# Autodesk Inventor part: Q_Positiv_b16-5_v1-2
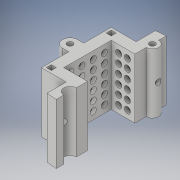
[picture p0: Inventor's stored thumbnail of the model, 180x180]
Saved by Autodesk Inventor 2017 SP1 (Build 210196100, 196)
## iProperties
Part Number: Q_Positiv_b16-5_v1-2
Material: Generisch
Document SubType Name: Modeling
Designer: haesner
Density: 1 g/cm^3
Appearance: Vorgabe
Part Number: Q_Positiv_b16-5_v1-2_3D-Druck
Author: haesner
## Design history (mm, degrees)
sketch "Skizze1"
  geometry: L1 (0, 9.5)-(-9.5, 9.5); L2 (-9.5, 9.5)-(-9.5, -9.5); L3 (-9.5, -9.5)-(0, -9.5); L4 (-26.9, 0)-(7.4, 0) reference; L5 (0, -9.5)-(0, -14); L6 (0, -22)-(0, -19); L7 (0, 22)-(0, 19); L8 (0, 14)-(0, 9.5); L9 (0, -30.8)-(0, 30.8) reference; C1 r 1.15 at (-16.5, 0); C2 r 1.15 at (0, 16.5); A1 r 22 centre (0, 0) between (0, 22) and (0, -22); A2 r 2.5 centre (0, -16.5) between (0, -14) and (0, -19); A3 r 2.5 centre (0, 16.5) between (0, 14) and (0, 19); 1 further point
  constraints: 14 end point, 6 point on circle, 5 centre point, 5 collinear, 3 point on line, 3 vertical, 2 coincident, 2 equal radius, 1 horizontal, 1 perpendicular, 1 other
  dimensions: "d1" = 22 radius of A1; "d5" = 2.3 diameter of C2; "d7" = 2.5 radius of A2; "d8" = 16.5 distance from line of L4 A3.centre (= d9); "d9" = 16.5 distance from line of L4 A2.centre; "d10" = 16.5 distance from line of C1.centre L9 (= d9); "d11" = 9.5 distance between parallel lines of L9 L2; "d18" = 19 distance of L1.end L2.end
extrude "Extrusion1" new body sketch "Skizze1" distance "d12" = 3; taper "d13" = 0 deg
sketch "Skizze3"
  geometry: L1 (-9.5, 9.5)-(0, 9.5); L2 (-9.5, -9.5)-(-9.5, 9.5); L3 (0, -9.5)-(-9.5, -9.5); L4 (0, -14)-(0, -9.5); L5 (0, 9.5)-(-9.5, 9.5); L6 (0, 9.5)-(0, 14); L7 (0, 19)-(0, 22) reference; L8 (0, -22)-(0, -19) reference; L9 (-26.9, 0)-(7.4, 0) reference; L10 (0, 9.5)-(0, 14) reference; L11 (-14, 14)-(-4, 14); L12 (-4, 14)-(-4, 21.633); L13 (-14, -14)-(-4, -14); L14 (-4, -14)-(-4, -21.633); L15 (0, -14)-(0, -9.5) reference; L16 (-9.5, 9.5)-(0, 9.5) reference; L17 (-9.5, -9.5)-(-9.5, 9.5) reference; L18 (0, -9.5)-(-9.5, -9.5) reference; L19 (-14, 14)-(-14, 3); L20 (-14, 3)-(-16.5, 3); L21 (-14, -14)-(-14, -3); L22 (-14, -3)-(-16.5, -3); C1 r 1.15 at (0, 16.5) reference; C2 r 1.15 at (-16.5, 0) reference; A1 r 2.5 centre (0, 16.5) between (0, 14) and (0, 19) reference; A2 r 22 centre (0, 0) between (0, 22) and (0, -22) reference; A3 r 2.5 centre (0, -16.5) between (0, -14) and (0, -19) reference; A4 r 22 centre (0, 0) between (0, 22) and (-4, 21.633); A5 r 22 centre (0, 0) between (-4, -21.633) and (0, -22); A6 r 3 centre (-16.5, 0) between (-16.5, 3) and (-16.5, -3); 3 further points
  constraints: 28 end point, 6 point on circle, 4 collinear, 3 centre point, 3 coincident, 3 horizontal, 3 perpendicular, 3 vertical, 2 equal length, 1 concentric, 2 other
  dimensions: "d74" = 4.5 distance between parallel lines of L3 L13 (= d19); "d75" = 4 distance between parallel lines of L4 L14; "d76" = 4.5 distance between parallel lines of L1 L11 (= d74); "d77" = 4 distance of the line from the sketch origin of L12 (= d75); "d95" = 3 radius of A6; "d96" = 4.5 distance between parallel lines of L2 L21 (= d76); "d97" = 6 distance between parallel lines of L22 L20
extrude "Extrusion3" join sketch "Skizze3" distance "d21" = 18; taper "d22" = 0 deg
sketch "Skizze5"
  geometry: L1 (0, 19)-(0, 22) reference; L2 (0, 9.5)-(0, 14) reference; L3 (-9.5, 9.5)-(0, 9.5) reference; L4 (-9.5, -9.5)-(-9.5, 9.5) reference; L5 (0, -9.5)-(-9.5, -9.5) reference; L6 (0, -14)-(0, -9.5) reference; L7 (0, -22)-(0, -19) reference; C1 r 1.15 at (0, 16.5) reference; C2 r 1.15 at (-16.5, 0) reference; A1 r 22 centre (0, 0) between (-4, 21.633) and (-4, -21.633) reference; A2 r 22 centre (0, 0) between (0, 22) and (-4, 21.633) reference; A3 r 2.5 centre (0, 16.5) between (0, 14) and (0, 19) reference; A4 r 2.5 centre (0, -16.5) between (0, -14) and (0, -19) reference; A5 r 22 centre (0, 0) between (-4, -21.633) and (0, -22) reference
extrude "Extrusion5" join sketch "Skizze5" distance "d27" = 3; taper "d28" = 0 deg
sketch "Skizze6"
  geometry: L1 (9.5, -13)-(1, -13); L2 (1, -13)-(1, -11); L3 (13, -9.5)-(13, 9.5); L4 (1, 11)-(1, 13); L5 (1, 13)-(9.5, 13); L6 (26.9, 0)-(-7.4, 0) reference; L7 (0, -30.8)-(0, 30.8) reference; L8 (1, -11)-(9.5, -11); L9 (11, -9.5)-(11, 9.5); L10 (9.5, 11)-(1, 11); L11 (9.5, 9.5)-(9.5, -9.5) reference; L12 (0, 9.5)-(9.5, 9.5) reference; L13 (9.5, -9.5)-(0, -9.5) reference; L14 (9.5, -13)-(9.5, -11); L15 (11, -9.5)-(13, -9.5); L16 (11, 9.5)-(13, 9.5); L17 (9.5, 11)-(9.5, 13); 1 further point
  constraints: 24 end point, 5 point on line, 3 horizontal, 3 perpendicular, 1 collinear, 1 vertical, 1 other
  dimensions: "d30" = 1 distance between parallel lines of L7 L2; "d78" = 1.5 distance between parallel lines of L11 L9; "d79" = 1.5 distance between parallel lines of L12 L10 (= d78); "d80" = 1.5 distance between parallel lines of L8 L13 (= d78); "d81" = 2 distance between parallel lines of L1 L8; "d82" = 2 distance between parallel lines of L3 L9 (= d81)
extrude "Extrusion6" cut sketch "Skizze6" distance "d32" = 23; taper "d33" = 0 deg
sketch "Skizze7"
  geometry: L1 (8, -6.6)-(4.5, -6.6); L2 (4.5, -6.6)-(4.5, -10.2); L3 (4.5, -10.2)-(8, -10.2); L4 (8, -10.2)-(8, -13.8); L5 (8, -13.8)-(4.5, -13.8); L6 (4.5, -13.8)-(4.5, -17.4); L7 (4.5, -17.4)-(8, -17.4); L8 (-15.9, 0)-(18.4, 0); L9 (11, 4.8)-(11, -28.8); L10 (8, -6.6)-(8, -3); L11 (8, -3)-(4.5, -3); L12 (8, -17.4)-(8, -21); L13 (8, -21)-(4.5, -21); 1 further point
  constraints: 26 end point, 7 parallel, 7 perpendicular, 3 point on line, 2 horizontal, 1 vertical
  dimensions: "d34" = 3.6 distance of L1.end L2.end; "d35" = 3.5 distance of L1.start L1.end; "d37" = 3 distance between parallel lines of L9 L4; "d45" = 3 distance between parallel lines of L8 L11
hole "Bohrung1" sketch "Skizze7" diameter "d38" = 2.5; stored, may be unused: countersink angle "d42" = 90 deg, drill point angle "d44" = 118 deg; dims "d39" = 6, "d40" = 4, "d41" = 2, "d43" = 22.25
sketch "Skizze8"
  geometry: L1 (-17.4, 2.75)-(-17.4, 7.25); L2 (-17.4, 7.25)-(-13.8, 7.25); L3 (-13.8, 7.25)-(-13.8, 2.75); L4 (-13.8, 2.75)-(-10.2, 2.75); L5 (-10.2, 2.75)-(-10.2, 7.25); L6 (-10.2, 7.25)-(-6.6, 7.25); L7 (-6.6, 7.25)-(-6.6, 2.75); L8 (-6.6, 2.75)-(-3, 2.75); L9 (-3, 2.75)-(-3, 7.25); L10 (-17.4, 11.75)-(-13.8, 11.75); L11 (-17.4, 11.75)-(-17.4, 16.25); L12 (-13.8, 11.75)-(-13.8, 16.25); L13 (-13.8, 16.25)-(-10.2, 16.25); L14 (-10.2, 16.25)-(-10.2, 11.75); L15 (-10.2, 11.75)-(-6.6, 11.75); L16 (-6.6, 11.75)-(-6.6, 16.25); L17 (-6.6, 16.25)-(-3, 16.25); L18 (-3, 16.25)-(-3, 11.75); L19 (4.2, 9.5)-(-25.2, 9.5) reference; L20 (0, -21.3)-(0, 40.3) reference; L21 (-17.4, 2.75)-(-21, 2.75); L22 (-21, 2.75)-(-21, 7.25); L23 (-17.4, 16.25)-(-21, 16.25); L24 (-21, 16.25)-(-21, 11.75); 1 further point
  constraints: 44 end point, 15 equal length, 12 perpendicular, 10 point on line, 4 vertical, 2 horizontal, 1 other
  dimensions: "d47" = 3.6 distance of L1.end L2.end; "d48" = 4.5 distance of L1.start L1.end; "d49" = 4.5 distance between parallel lines of L10 L2; "d50" = 3 distance between parallel lines of L20 L9
hole "Bohrung2" sketch "Skizze8" diameter "d51" = 2.5; stored, may be unused: countersink angle "d55" = 90 deg, drill point angle "d57" = 118 deg; dims "d52" = 6, "d53" = 4, "d54" = 2, "d56" = 1.5
sketch "Skizze11"
  geometry: L1 (9, 2.5)-(9, -30.5); L2 (-3, -44.8)-(-3, 16.8) reference; L3 (-7.8, -14)-(25.8, -14) reference; 1 further point
  constraints: 2 end point, 1 symmetric about line
  dimensions: "d83" = 12 distance between parallel lines of L2 L1; "d84" = 33 distance of L1.start L1.end
hole "Bohrung3" sketch "Skizze11" at (9, 2.5), (9, -30.5) diameter "d85" = 2.3; stored, may be unused: countersink angle "d89" = 90 deg, drill point angle "d91" = 118 deg; dims "d86" = 6, "d87" = 4, "d88" = 2, "d90" = 8
sketch "Skizze12"
  geometry: L1 (-4, 21.633)-(-4, 14) reference; L2 (-4, -14)-(-4, -21.633) reference; L3 (-26.9, 0)-(7.4, 0) reference; L4 (-4, 14)-(-14, 14) reference; L5 (-14, 14)-(-14, 3) reference; L6 (-14, 3)-(-16.5, 3) reference; L7 (-16.5, -3)-(-14, -3) reference; L8 (-14, -3)-(-14, -14) reference; L9 (-14, -14)-(-4, -14) reference; A1 r 22 centre (0, 0) between (0, 22) and (0, -22) reference; A2 r 3 centre (-16.5, 0) between (-16.5, 3) and (-16.5, -3) reference; 2 further points
  constraints: 1 point on circle
extrude "Extrusion9" cut sketch "Skizze12" distance "d93" = 30; taper "d94" = 0 deg
sketch "Skizze13"
  geometry: L1 (11, -13)-(13, -13); L2 (13, -13)-(13, -11); L3 (13, -11)-(11, -11); L4 (11, -11)-(11, -13); L5 (11, 11)-(13, 11); L6 (13, 11)-(13, 13); L7 (13, 13)-(11, 13); L8 (11, 13)-(11, 11); L9 (9.5, -11)-(9.5, -13) reference; L10 (13, -9.5)-(11, -9.5) reference; L11 (11, 9.5)-(13, 9.5) reference; L12 (9.5, 13)-(9.5, 11) reference; 1 further point
  constraints: 16 end point, 5 point on line, 4 parallel, 3 equal length, 2 horizontal, 2 perpendicular
extrude "Extrusion10" cut sketch "Skizze13" distance "d98" = 40; taper "d99" = 0 deg
sketch "Skizze14"
  geometry: L1 (9.5, -11)-(9.5, -13) reference; L2 (11, -13)-(11, -11) reference; L3 (13, -9.5)-(11, -9.5) reference; L4 (11, -11)-(13, -11) reference; L5 (13, 11)-(11, 11) reference; L6 (11, 9.5)-(13, 9.5) reference; L7 (9.5, 13)-(9.5, 11) reference; L8 (11, 11)-(11, 13) reference; L9 (11, -13)-(9.5, -13); L10 (9.5, -11)-(11, -11); L11 (11, -9.5)-(11, -11); L12 (13, -11)-(13, -9.5); L13 (11, 9.5)-(11, 11); L14 (13, 11)-(13, 9.5); L15 (11, 13)-(11, 11) reference; L16 (11, 11)-(9.5, 11); L17 (9.5, 13)-(11, 13); 1 further point
  constraints: 16 end point, 5 parallel, 2 perpendicular, 1 horizontal
extrude "Extrusion11" cut sketch "Skizze14" distance "d100" = 10; taper "d101" = 0 deg
node "Volumenkörper1"
other parameters: "d19" = 4.5 (= d20), "d20" = 4.5
